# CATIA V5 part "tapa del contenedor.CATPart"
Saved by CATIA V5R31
Part number: tapa del contenedor
Bounding box of the stored display mesh (mm): x -68.7 to 68.7, y -68.25 to 68.25, z 0 to 3.3
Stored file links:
  C:\Users\189361\Desktop\tapa del contenedor.CATPart
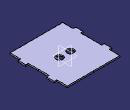
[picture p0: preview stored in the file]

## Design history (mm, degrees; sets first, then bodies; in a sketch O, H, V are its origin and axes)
Set1 "sketch"
  Sketch1 on xy-plane, origin (0, 0, 0), H (1, 0, 0), V (0, 1, 0)
    point P1 (0, -68.25)
    line L1 (0, -68.25) -> (-62.7, -68.25)
    point P2 (-62.7, -68.25)
    line L2 (-62.7, -68.25) -> (-62.7, -43)
    point P3 (-62.7, -43)
    line L3 (-62.7, -43) -> (-68.7, -43)
    point P4 (-68.7, -43)
    line L4 (-68.7, -43) -> (-68.7, -25)
    point P5 (-68.7, -25)
    line L5 (-68.7, -25) -> (-62.7, -25)
    point P6 (-62.7, -25)
    line L6 (-62.7, -25) -> (-62.7, 0)
    point P7 (-62.7, 0)
    point P8 (0, -68.25)
    point P9 (62.7, -68.25)
    point P10 (62.7, -43)
    point P11 (68.7, -43)
    point P12 (68.7, -25)
    point P13 (62.7, -25)
    line L7 (0, -68.25) -> (62.7, -68.25)
    line L8 (62.7, -68.25) -> (62.7, -43)
    line L9 (62.7, -43) -> (68.7, -43)
    line L10 (68.7, -43) -> (68.7, -25)
    line L11 (68.7, -25) -> (62.7, -25)
    point P14 (62.7, 0)
    line L12 (62.7, -25) -> (62.7, 0)
    point P15 (0, 68.25)
    point P16 (-62.7, 68.25)
    point P17 (-62.7, 43)
    point P18 (-68.7, 43)
    point P19 (-68.7, 25)
    point P20 (-62.7, 25)
    point P21 (0, 68.25)
    point P22 (62.7, 68.25)
    point P23 (62.7, 43)
    point P24 (68.7, 43)
    point P25 (68.7, 25)
    point P26 (62.7, 25)
    line L13 (0, 68.25) -> (-62.7, 68.25)
    line L14 (-62.7, 68.25) -> (-62.7, 43)
    line L15 (-62.7, 43) -> (-68.7, 43)
    line L16 (-68.7, 43) -> (-68.7, 25)
    line L17 (-68.7, 25) -> (-62.7, 25)
    line L18 (0, 68.25) -> (62.7, 68.25)
    line L19 (62.7, 68.25) -> (62.7, 43)
    line L20 (62.7, 43) -> (68.7, 43)
    line L21 (68.7, 43) -> (68.7, 25)
    line L22 (68.7, 25) -> (62.7, 25)
    point P27 (-62.7, 0)
    line L23 (-62.7, 25) -> (-62.7, 0)
    point P28 (62.7, 0)
    line L24 (62.7, 25) -> (62.7, 0)
    distance H L1 = 68.25
    distance H L5 = 25
    length L4 = 18
    length L5 = 6
    length L1 = 62.7
    coincidence: P1 V, P6 L2, P7 H, P1 P8, P7 P27, P14 P28, P15 P21
    horizontal: L1 H, L3 H, L5 H
    vertical: L2 V, L4 V, L6 V
    symmetry: P1 P8 V, P2 P9 V, P3 P10 V, P4 P11 V, P5 P12 V, P6 P13 V, L1 L7 V, L2 L8 V, L3 L9 V, L4 L10 V, L5 L11 V, P7 P14 V, L6 L12 V, P1 P15 H, P2 P16 H, P3 P17 H, P4 P18 H, P5 P19 H, P6 P20 H, P8 P21 H, P9 P22 H, P10 P23 H, P11 P24 H, P12 P25 H, P13 P26 H, L1 L13 H, L2 L14 H, L3 L15 H, L4 L16 H, L5 L17 H, L7 L18 H, L8 L19 H, L9 L20 H, L10 L21 H, L11 L22 H, P7 P27 H, L6 L23 H, P14 P28 H, L12 L24 H
  Sketch2 on end face of Pad1, origin (0, 0, 3.3), H (1, 0, 0), V (0, 1, 0)
    circle A1 centre (13, 0) radius 8.25
    point P1 (13, 0)
    circle A2 centre (-13, 0) radius 8.25
    radius A1 = 8.25
    distance P1 V = 13
    coincidence: P1 H
    symmetry: A1 A2 V
Body1 (main body)
  Pad1: profile Sketch1, direction (0, 0, 1), length 3.3
  Pocket1: profile Sketch2, direction (0, 0, -1), length 3.3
